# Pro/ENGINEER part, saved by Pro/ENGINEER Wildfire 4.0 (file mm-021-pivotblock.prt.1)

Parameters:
  METRIC = "NO"

Other parameters: PITCH, DRILL_POINT_ANGLE, DRILL_DEPTH, DRILL_DIAMETER, THREAD_DIAMETER, THREADS_PER_INCH, THREAD_DEPTH, THREAD_LENGTH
